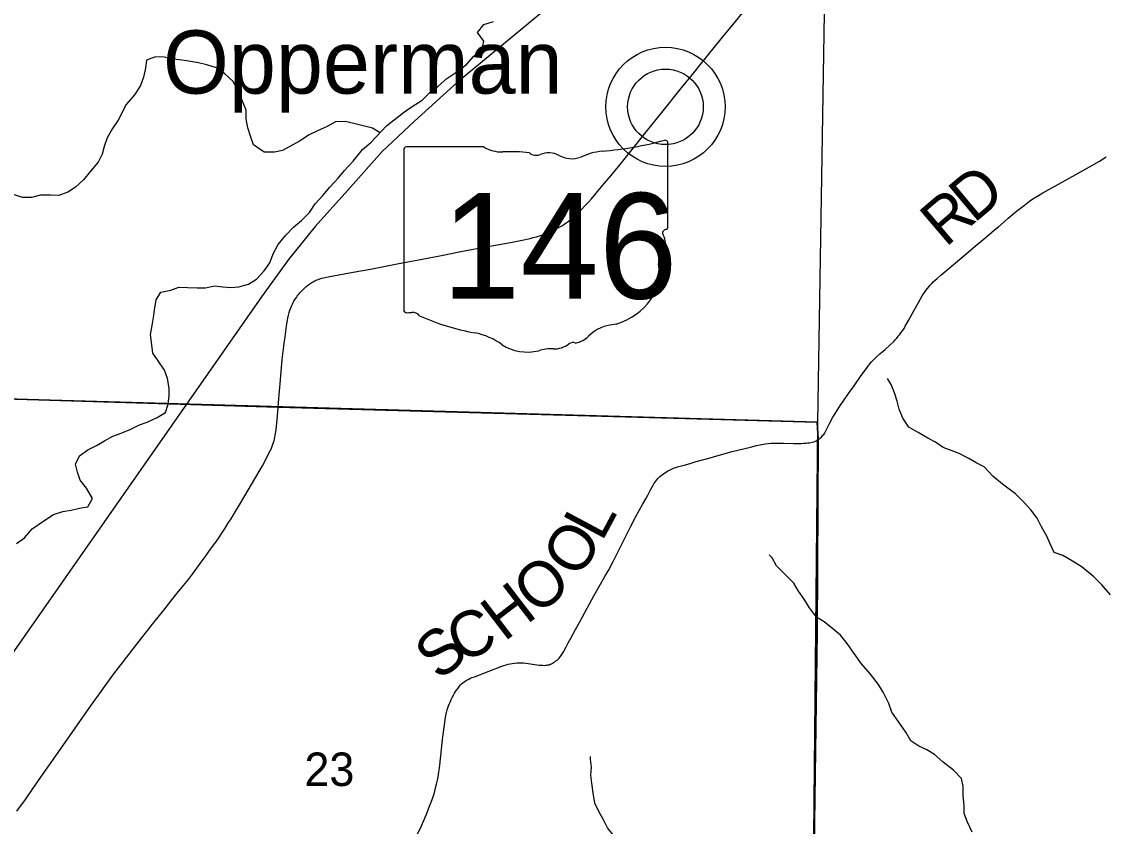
# Model space of a CAD drawing. Extents: x 0 to 34, y 0 to 22.
# Drawn here: x 2.794 to 4.145, y 18.682 to 19.687 of the extents above; entities that cross this region are included whole.
import ezdxf

# ---------------------------------------------------------------- set-up
doc = ezdxf.new("R2010")
doc.units = 0
for name, color, linetype in [('GM_X_Corporation', 7, 'Continuous'), ('GM_X_Minor_River', 7, 'Continuous'), ('GM_X_Rail_Line', 7, 'Continuous'), ('GM_X_Section_Text', 7, 'Continuous'), ('GM_X_State_Location', 7, 'Continuous'), ('GM_X_State_Route', 7, 'Continuous'), ('GM_X_State_Shield', 7, 'Continuous'), ('GM_X_Township_Road', 7, 'Continuous'), ('GM_X_Township_Road_Text', 7, 'Continuous'), ('GM_X_Unincorporated', 7, 'Continuous'), ('GM_X_Unincorporated_Location', 7, 'Continuous'), ('GM_X_Unincorporated_Text', 7, 'Continuous')]:
    doc.layers.add(name, color=color, linetype=linetype)

msp = doc.modelspace()

# ---------------------------------------------------------------- linework, layer by layer
at = {"layer": 'GM_X_Corporation'}
for points in [[(4.7823, 18.128), (4.0508, 18.1454), (3.7812, 18.1547), (3.7776, 18.3354), (3.7807, 18.4204), (3.7875, 18.9248), (3.7889, 19.1658), (3.7877, 19.187), (3.1142, 19.2057), (2.7749, 19.2162), (2.7798, 20.0198), (2.7831, 20.242), (2.7976, 21.3075), (2.7987, 21.3734), (1.6311, 21.3734), (1.6311, 16.1731), (2.3716, 16.1532), (2.3935, 16.1523), (3.7652, 16.1115), (4.1576, 16.1007)], [(8.4311, 21.3734), (2.7987, 21.3734), (2.7976, 21.3075), (2.7831, 20.242), (2.7798, 20.0198), (2.7749, 19.2162), (3.1142, 19.2057), (3.7877, 19.187), (3.7889, 19.1658), (3.7875, 18.9248), (3.7807, 18.4204), (3.7776, 18.3354), (3.7812, 18.1547), (4.0508, 18.1454), (4.7823, 18.128)]]:
    msp.add_lwpolyline(points, dxfattribs=at)
for points in [[(3.8046, 20.2092), (3.7879, 19.187), (2.7721, 19.2162), (2.7815, 20.2421)], [(3.7879, 19.187), (3.7781, 18.1522), (2.7572, 18.1961), (2.7721, 19.2162)]]:
    msp.add_lwpolyline(points, close=True, dxfattribs=at)
at = {"layer": 'GM_X_Minor_River'}
for points in [[(3.0555, 19.3554), (3.0653, 19.3563), (3.0777, 19.3594), (3.0875, 19.3656), (3.0969, 19.3763), (3.1043, 19.3862), (3.1084, 19.3973), (3.1147, 19.4091), (3.1241, 19.4206), (3.1338, 19.4305), (3.1436, 19.4389), (3.1537, 19.4489), (3.1608, 19.46), (3.1705, 19.4703), (3.1791, 19.4806), (3.1896, 19.4917), (3.1975, 19.5013), (3.2083, 19.5131), (3.2199, 19.5276), (3.2304, 19.5365), (3.2499, 19.5571), (3.2709, 19.574), (3.2818, 19.5813), (3.2942, 19.5894), (3.3044, 19.5994), (3.3145, 19.6067), (3.3254, 19.6163), (3.3389, 19.6255), (3.3498, 19.6339), (3.3588, 19.6443), (3.3689, 19.6519), (3.3715, 19.663), (3.3634, 19.6739), (3.3713, 19.6838), (3.3833, 19.6877)], [(3.2419, 19.5486), (3.2322, 19.5543), (3.2208, 19.5572), (3.2106, 19.5597), (3.1981, 19.5626), (3.186, 19.5621), (3.1751, 19.556), (3.1645, 19.5513), (3.1532, 19.5459), (3.1412, 19.5382), (3.1198, 19.5266), (3.1099, 19.5242), (3.0971, 19.5245), (3.0838, 19.5334), (3.0803, 19.5432), (3.0768, 19.5549), (3.0748, 19.5659), (3.0747, 19.5769), (3.0697, 19.589), (3.0658, 19.5999), (3.0585, 19.6127), (3.0479, 19.6224), (3.0376, 19.6299), (3.0255, 19.6336), (3.0152, 19.6361), (3.0001, 19.6386), (2.9846, 19.6407), (2.9721, 19.6432), (2.9615, 19.6435), (2.9502, 19.6392), (2.9491, 19.6294), (2.9466, 19.618), (2.9425, 19.6077), (2.9351, 19.5959), (2.9246, 19.584), (2.9149, 19.5642), (2.9078, 19.5539), (2.9011, 19.5421), (2.8971, 19.5315), (2.8949, 19.522), (2.8897, 19.5117), (2.8803, 19.5006), (2.8713, 19.4899), (2.8616, 19.4807), (2.8518, 19.4745), (2.8405, 19.4702), (2.8303, 19.4705), (2.8178, 19.4708), (2.8065, 19.4676), (2.7952, 19.4679), (2.7815, 19.4723)], [(2.7876, 19.0355), (2.7977, 19.0428), (2.8075, 19.0539), (2.8221, 19.0639), (2.8341, 19.0716), (2.8455, 19.0755), (2.856, 19.0772), (2.8666, 19.0795), (2.8768, 19.0815), (2.8827, 19.0918), (2.8754, 19.1046), (2.8674, 19.1148), (2.8639, 19.1246), (2.8616, 19.1348), (2.8664, 19.1451), (2.8769, 19.1524), (2.8878, 19.1578), (2.8976, 19.164), (2.9081, 19.1698), (2.9183, 19.1733), (2.9304, 19.1783), (2.9413, 19.1837), (2.9511, 19.1873), (2.9635, 19.1931), (2.974, 19.1992), (2.977, 19.2095), (2.9784, 19.2201), (2.9783, 19.2296), (2.9763, 19.2417), (2.9728, 19.2519), (2.9648, 19.2636), (2.9579, 19.2733), (2.9567, 19.2839), (2.955, 19.2968), (2.9572, 19.3078), (2.959, 19.3177), (2.9601, 19.3272), (2.9622, 19.3401), (2.9682, 19.3496), (2.9806, 19.352), (2.9904, 19.3559), (3.0014, 19.3552), (3.0135, 19.355), (3.0237, 19.3551), (3.035, 19.3575), (3.0456, 19.3561), (3.0555, 19.3554)], [(4.1539, 18.9714), (4.1432, 18.9838), (4.1333, 18.9939), (4.1185, 19.0059), (4.1067, 19.0137), (4.0945, 19.0204), (4.0835, 19.0245), (4.0785, 19.035), (4.0743, 19.0448), (4.0678, 19.0565), (4.0624, 19.0671), (4.0543, 19.0776), (4.0456, 19.0873), (4.0353, 19.0978), (4.0193, 19.1098), (4.0071, 19.1195), (3.9964, 19.1312), (3.9869, 19.136), (3.9771, 19.1416), (3.9649, 19.1479), (3.955, 19.1516), (3.9448, 19.1556), (3.9353, 19.1623), (3.9258, 19.1672), (3.9136, 19.1742), (3.9022, 19.1809), (3.8946, 19.1922), (3.8899, 19.2032), (3.8876, 19.2134), (3.8841, 19.2236), (3.8802, 19.2341), (3.8756, 19.2417)], [(3.9811, 18.6752), (3.9753, 18.6873), (3.9711, 18.6982), (3.9714, 18.7081), (3.9701, 18.7202), (3.97, 18.7319), (3.9681, 18.7421), (3.9581, 18.7523), (3.9452, 18.7624), (3.9341, 18.7721), (3.9246, 18.7777), (3.9148, 18.7825), (3.9045, 18.7892), (3.8984, 18.7998), (3.8896, 18.8126), (3.8811, 18.825), (3.8773, 18.8359), (3.87, 18.8499), (3.8642, 18.8596), (3.8543, 18.8724), (3.8432, 18.8852), (3.834, 18.898), (3.8252, 18.9108), (3.8168, 18.9209), (3.8073, 18.9288), (3.7962, 18.9377), (3.7867, 18.9437), (3.7779, 18.9553), (3.7714, 18.9659), (3.7642, 18.976), (3.7584, 18.9862), (3.7473, 18.9971), (3.737, 19.0076), (3.7313, 19.0177), (3.7278, 19.0215)], [(3.6845, 18.5408), (3.6494, 18.5626), (3.638, 18.5709), (3.6278, 18.5757), (3.6175, 18.5831), (3.6061, 18.591), (3.5973, 18.6023), (3.5866, 18.6139), (3.574, 18.6244), (3.5615, 18.6371), (3.5523, 18.648), (3.5435, 18.6589), (3.5347, 18.6694), (3.5259, 18.6803), (3.5209, 18.6905), (3.5152, 18.7007), (3.5102, 18.7112), (3.5078, 18.7241), (3.5062, 18.7362), (3.5049, 18.746), (3.506, 18.7562), (3.5044, 18.7661), (3.5047, 18.7695)]]:
    msp.add_lwpolyline(points, dxfattribs=at)
at = {"layer": 'GM_X_Rail_Line'}
msp.add_lwpolyline([(4.1788, 20.304), (4.0429, 20.1945), (3.3384, 19.6119), (3.2847, 19.5633), (3.2446, 19.5253), (3.2015, 19.4768), (3.1607, 19.4315), (3.1275, 19.3905), (3.0936, 19.3436), (2.5732, 18.599), (2.0707, 17.885), (2.0334, 17.8382), (1.9924, 17.7972), (1.9547, 17.7644), (1.7027, 17.5707), (1.6311, 17.5139)], dxfattribs=at)
at = {"layer": 'GM_X_State_Route'}
for points in [[(3.1144, 19.2051), (3.1149, 19.2116), (3.1173, 19.2401), (3.1197, 19.2654), (3.122, 19.2852), (3.1231, 19.2938), (3.124, 19.3005), (3.125, 19.3072), (3.1259, 19.3126), (3.1267, 19.317), (3.1276, 19.3207), (3.1285, 19.3241), (3.1293, 19.327), (3.1304, 19.33), (3.1312, 19.3322), (3.1323, 19.3345), (3.1332, 19.3364), (3.1343, 19.3382), (3.1357, 19.3406), (3.1373, 19.3429), (3.1384, 19.3445), (3.1397, 19.3461), (3.1407, 19.3474), (3.1418, 19.3487), (3.1436, 19.3507), (3.1456, 19.3527), (3.1474, 19.3545), (3.1491, 19.3561), (3.1512, 19.3578), (3.1535, 19.3594), (3.1557, 19.361), (3.1582, 19.3624), (3.1605, 19.3636), (3.1627, 19.3647), (3.1648, 19.3655), (3.1667, 19.3662), (3.1689, 19.3669), (3.1713, 19.3675), (3.1748, 19.3683), (3.1791, 19.3691), (3.2084, 19.3745), (3.2297, 19.3784), (3.2633, 19.3848), (3.2925, 19.3905), (3.3205, 19.3959), (3.3406, 19.3999), (3.3516, 19.402), (3.3693, 19.4052), (3.3858, 19.4081), (3.4047, 19.4117), (3.4212, 19.4149), (3.4253, 19.4157), (3.4292, 19.4166), (3.4332, 19.4176), (3.437, 19.4186), (3.441, 19.4199), (3.4447, 19.4212), (3.449, 19.4228), (3.4534, 19.4247), (3.4571, 19.4264), (3.4608, 19.4282), (3.4635, 19.4295), (3.4663, 19.4311), (3.469, 19.4325), (3.4715, 19.4341), (3.4741, 19.4359), (3.4768, 19.4379), (3.4791, 19.4397), (3.4817, 19.4418), (3.4878, 19.4473), (3.4935, 19.4529), (3.4977, 19.4574), (3.502, 19.4621), (3.5057, 19.4662), (3.5118, 19.4733), (3.5222, 19.4857), (3.5298, 19.4947), (3.5417, 19.5091), (3.5601, 19.5318), (3.5708, 19.5455), (3.5831, 19.561), (3.5936, 19.5741), (3.6181, 19.6048), (3.6241, 19.612), (3.6281, 19.6167), (3.6337, 19.6233), (3.6432, 19.6355), (3.6679, 19.6659), (3.684, 19.6857), (3.7075, 19.7146)], [(2.7882, 18.7014), (2.7989, 18.7159), (2.8078, 18.7286), (2.819, 18.745), (2.8319, 18.7633), (2.8426, 18.7786), (2.8793, 18.831), (2.89, 18.8462), (2.9006, 18.8609), (2.9093, 18.8729), (2.9208, 18.8876), (2.9395, 18.9116), (2.9594, 18.937), (2.9718, 18.9525), (2.9865, 18.971), (2.9964, 18.983), (3.0025, 18.9908), (3.0074, 18.9972), (3.0172, 19.0107), (3.0246, 19.0207), (3.0289, 19.0268), (3.0366, 19.0374), (3.0404, 19.0427), (3.0443, 19.0486), (3.0484, 19.0549), (3.0527, 19.0617), (3.0557, 19.0665), (3.0586, 19.0712), (3.0662, 19.084), (3.0769, 19.1022), (3.0949, 19.1327), (3.1014, 19.1447), (3.1039, 19.1499), (3.1049, 19.1519), (3.1061, 19.1545), (3.1072, 19.157), (3.1081, 19.1595), (3.1088, 19.1616), (3.1094, 19.1639), (3.11, 19.1662), (3.1105, 19.1684), (3.1109, 19.1707), (3.1113, 19.1729), (3.1119, 19.1776), (3.1133, 19.1906), (3.1144, 19.2051)]]:
    msp.add_lwpolyline(points, dxfattribs=at)
at = {"layer": 'GM_X_State_Shield'}
for p, q in [((3.6011, 19.4312), (3.6011, 19.5359)), ((3.2715, 19.5275), (3.2715, 19.3274)), ((3.3713, 19.5309), (3.2748, 19.5309)), ((3.6011, 19.4312), (3.6011, 19.4312))]:
    msp.add_line(p, q, dxfattribs=at)
for centre, major_axis, start_param, end_param in [((3.4837, 19.8038), (0.3495, 0), 4.814394, 5.042369), ((3.5975, 19.5363), (0.00367, 0), 6.141152, 7.989035), ((3.2753, 19.5279), (0.00382, 0), 1.712693, 3.28349), ((3.3943, 19.5542), (0.037, 0), 4.042523, 4.731795), ((3.4066, 19.4186), (0.133, 0), 1.404758, 1.657858), ((3.4367, 19.529), (0.0107, 0), 3.836095, 5.185415), ((3.4524, 19.5058), (0.0222, 0), 0.950623, 2.079405), ((3.4811, 19.5376), (0.0267, 0), 4.081561, 5.145723), ((3.5283, 19.4698), (0.0703, 0), 1.699011, 2.107814), ((3.6003, 19.4235), (0.00568, 0), 1.883978, 3.671073), ((3.5972, 19.4308), (0.00393, 0), 5.05454, 6.418171), ((3.5641, 19.4103), (0.0341, 0), 5.934695, 6.695948), ((3.6143, 19.3874), (0.0248, 0), 2.387724, 3.262537), ((3.5033, 19.3741), (0.0874, 0), 5.101752, 6.440018), ((3.2753, 19.3269), (0.00385, 0), 3.00124, 4.508301), ((3.2759, 19.3474), (0.0294, 0), 4.665946, 4.897461), ((3.2819, 19.3158), (0.0106, 0), 0.519207, 1.627899), ((3.4158, 19.4956), (0.2524, 0), 4.195997, 4.488961), ((3.5402, 19.2712), (0.0479, 0), 1.647645, 2.488434), ((3.3405, 19.2375), (0.079, 0), 0.823519, 1.323587), ((3.4795, 19.308), (0.0282, 0), 4.937069, 5.64225), ((3.4259, 19.3148), (0.0501, 0), 4.026481, 4.996735), ((3.4549, 19.2457), (0.0412, 0), 1.495662, 1.94098), ((3.4585, 19.2999), (0.0267, 0), 4.691044, 5.507374), ((3.4827, 19.2805), (0.00752, 0), 1.147584, 2.315152)]:
    msp.add_ellipse(centre, major_axis=major_axis, ratio=0.8, start_param=start_param, end_param=end_param, dxfattribs=at)
at = {"layer": 'GM_X_Township_Road'}
for points in [[(3.7884, 19.1649), (3.7891, 19.1653), (3.7907, 19.1665), (3.7919, 19.1674), (3.7929, 19.1684), (3.7939, 19.1695), (3.7949, 19.1707), (3.7958, 19.1718), (3.7967, 19.1731), (3.7981, 19.1755), (3.7994, 19.1779), (3.8036, 19.1862), (3.8074, 19.1933), (3.8096, 19.197), (3.8152, 19.206), (3.8221, 19.2162), (3.8281, 19.2247), (3.8338, 19.2326), (3.8419, 19.244), (3.8501, 19.2556), (3.8518, 19.2581), (3.8537, 19.2604), (3.8557, 19.2626), (3.8577, 19.2647), (3.8613, 19.2682), (3.866, 19.2723), (3.8726, 19.2779), (3.879, 19.2837), (3.8834, 19.288), (3.8855, 19.2902), (3.8873, 19.2922), (3.889, 19.2944), (3.8906, 19.2963), (3.8923, 19.2986), (3.8942, 19.3013), (3.8961, 19.3043), (3.8977, 19.307), (3.9018, 19.3141), (3.9086, 19.327), (3.9141, 19.3368), (3.9189, 19.3448), (3.9234, 19.3515), (3.9254, 19.3542), (3.927, 19.3563), (3.9288, 19.3583), (3.9307, 19.3604), (3.9327, 19.3624), (3.9351, 19.3645), (3.9375, 19.3666), (3.9421, 19.3707), (3.9472, 19.375), (3.9627, 19.3884), (3.9736, 19.3975), (3.985, 19.4069), (3.9944, 19.4148), (4.0023, 19.4214), (4.0093, 19.4273), (4.014, 19.4313), (4.021, 19.4374), (4.0262, 19.4419), (4.0367, 19.4506), (4.0465, 19.4583), (4.053, 19.4632), (4.0559, 19.4652), (4.0592, 19.4674), (4.0641, 19.4703), (4.0693, 19.4734), (4.1003, 19.4906), (4.1279, 19.5061), (4.1401, 19.5133), (4.1484, 19.5185)], [(3.288, 18.6716), (3.2934, 18.6827), (3.2977, 18.6924), (3.3006, 18.6994), (3.3037, 18.7073), (3.3056, 18.7123), (3.3073, 18.7172), (3.3088, 18.7216), (3.3101, 18.726), (3.3112, 18.7304), (3.3124, 18.735), (3.3135, 18.7398), (3.3143, 18.7441), (3.3153, 18.75), (3.3161, 18.7551), (3.3179, 18.7705), (3.3199, 18.7908), (3.321, 18.7998), (3.323, 18.8153), (3.324, 18.8209), (3.3248, 18.8243), (3.3257, 18.8276), (3.3265, 18.8303), (3.3274, 18.833), (3.3284, 18.8356), (3.3296, 18.8382), (3.3307, 18.8407), (3.332, 18.8433), (3.3334, 18.846), (3.3349, 18.8488), (3.3373, 18.8525), (3.3392, 18.855), (3.3411, 18.8575), (3.3424, 18.859), (3.3437, 18.8603), (3.3452, 18.8615), (3.3467, 18.8628), (3.3482, 18.8638), (3.3499, 18.8648), (3.3517, 18.8658), (3.3538, 18.8668), (3.3565, 18.868), (3.3596, 18.8692), (3.3938, 18.8823), (3.3964, 18.8832), (3.3992, 18.884), (3.4017, 18.8847), (3.4041, 18.8852), (3.4069, 18.8857), (3.4097, 18.8861), (3.4125, 18.8863), (3.4154, 18.8864), (3.418, 18.8864), (3.421, 18.8863), (3.4237, 18.8861), (3.4266, 18.8857), (3.4407, 18.8837), (3.4427, 18.8835), (3.445, 18.8834), (3.4467, 18.8833), (3.4486, 18.8834), (3.45, 18.8836), (3.4515, 18.8839), (3.4529, 18.8842), (3.4543, 18.8847), (3.4557, 18.8852), (3.457, 18.8859), (3.4585, 18.8868), (3.4601, 18.8877), (3.4615, 18.8888), (3.4629, 18.8899), (3.4654, 18.8925), (3.468, 18.8958), (3.4695, 18.898), (3.471, 18.9004), (3.474, 18.9058), (3.4769, 18.9113), (3.4801, 18.9172), (3.486, 18.9282), (3.4913, 18.9379), (3.498, 18.9504), (3.5086, 18.97), (3.5153, 18.9819), (3.5225, 18.9942), (3.5273, 19.0028), (3.5329, 19.013), (3.5392, 19.0254), (3.5451, 19.0374), (3.5505, 19.0479), (3.5545, 19.0562), (3.5613, 19.0694), (3.5657, 19.0777), (3.5694, 19.0841), (3.5738, 19.0915), (3.5761, 19.0959), (3.5775, 19.0986), (3.5795, 19.1025), (3.5812, 19.1056), (3.5828, 19.1084), (3.5838, 19.1102), (3.5848, 19.1118), (3.586, 19.1134), (3.5874, 19.1152), (3.5886, 19.1166), (3.5899, 19.1179), (3.5912, 19.1191), (3.5927, 19.1204), (3.5942, 19.1215), (3.5957, 19.1227), (3.5974, 19.1239), (3.5993, 19.1252), (3.6008, 19.126), (3.6024, 19.1269), (3.6039, 19.1276), (3.6059, 19.1286), (3.6082, 19.1295), (3.6106, 19.1304), (3.6133, 19.1312), (3.6217, 19.1336), (3.6292, 19.1356), (3.6366, 19.1378), (3.654, 19.1426), (3.6593, 19.1442), (3.6815, 19.1503), (3.7044, 19.1561), (3.7117, 19.1578), (3.7184, 19.1592), (3.7227, 19.16), (3.7263, 19.1604), (3.7302, 19.1607), (3.7329, 19.1609), (3.7358, 19.161), (3.7458, 19.1609), (3.7582, 19.1604), (3.7644, 19.1604), (3.7675, 19.1605), (3.7707, 19.1607), (3.7734, 19.1609), (3.7754, 19.1611), (3.7779, 19.1614), (3.7796, 19.1617), (3.7813, 19.162), (3.783, 19.1624), (3.7846, 19.1629), (3.7862, 19.1636), (3.7877, 19.1645), (3.7884, 19.1649)]]:
    msp.add_lwpolyline(points, dxfattribs=at)
at = {"layer": 'GM_X_Unincorporated'}
for radius in [0.0744, 0.0472]:
    msp.add_circle((3.5982, 19.581), radius, dxfattribs=at)
at = {"layer": 'GM_X_Unincorporated_Location'}
msp.add_line((3.5982, 19.581), (3.5982, 19.581), dxfattribs=at)

# ---------------------------------------------------------------- texts
at = {"layer": 'GM_X_Section_Text'}
msp.add_text('23', height=0.04186, rotation=0, dxfattribs=at).set_placement((3.1474, 18.7326))
at = {"layer": 'GM_X_State_Location'}
for s in ['s', 'r']:
    msp.add_text(s, height=0.000189, dxfattribs=at).set_placement((3.4326, 19.4141))
msp.add_text('146', height=0.000189, rotation=0, dxfattribs=at).set_placement((3.3658, 19.4004))
at = {"layer": 'GM_X_State_Shield'}
msp.add_text('146', height=0.13184, dxfattribs=at).set_placement((3.319, 19.3415))
at = {"layer": 'GM_X_Township_Road_Text'}
for s, rotation, p in [('D', 39.9436, (3.9833, 19.4348)), ('R', 40.5287, (3.9479, 19.4046)), ('L', 61.8733, (3.5188, 19.0367)), ('O', 56.8884, (3.4888, 18.9901)), ('O', 40.1559, (3.4386, 18.9444)), ('H', 37.5198, (3.3967, 18.9121)), ('C', 24.201, (3.3418, 18.8856)), ('S', 40.9834, (3.3165, 18.8628))]:
    msp.add_text(s, height=0.0568, rotation=rotation, dxfattribs=at).set_placement(p)
at = {"layer": 'GM_X_Unincorporated_Text'}
msp.add_text('Opperman', height=0.07898, rotation=0, dxfattribs=at).set_placement((2.9708, 19.5975))

doc.saveas('drawing.dxf')
